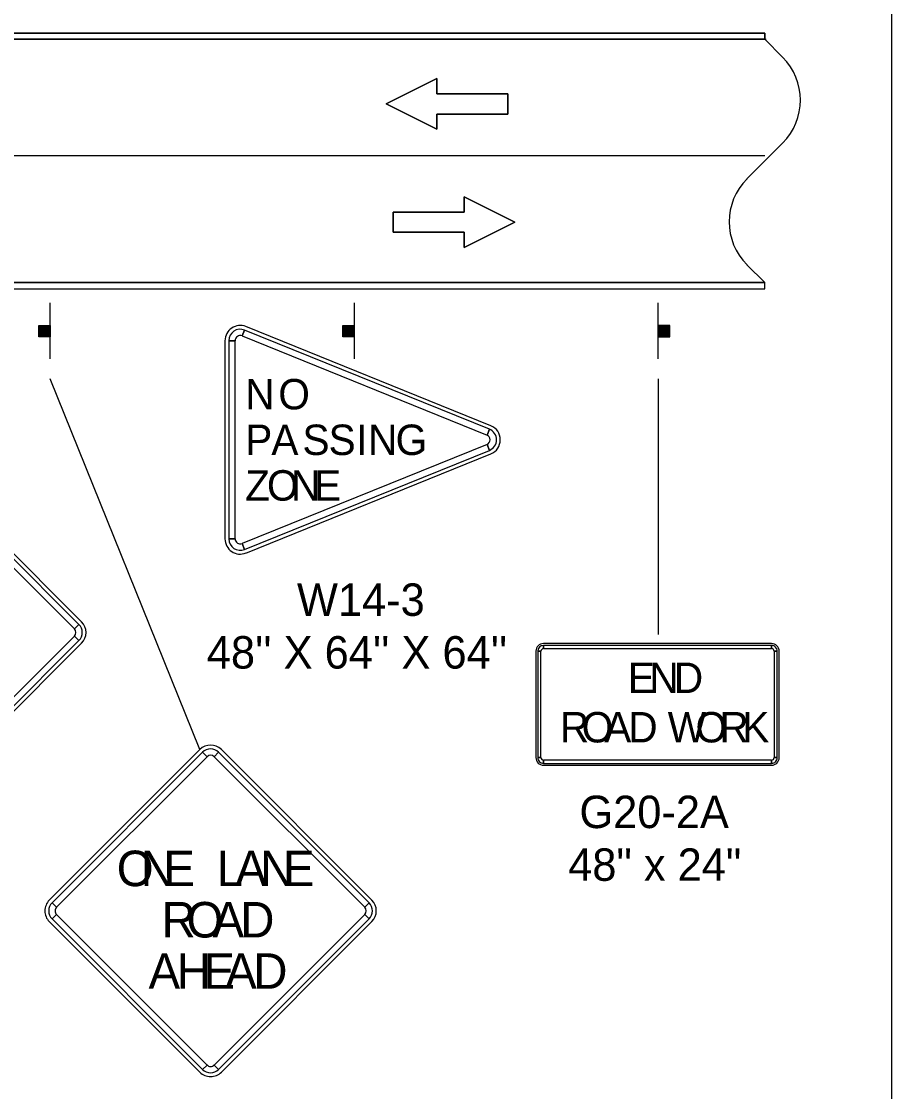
# Model space of a CAD drawing. Extents: x -2134934 to -2119606, y -2139046 to -2137036.
# Drawn here: x -2132229 to -2131799, y -2138064 to -2137536 of the extents above; entities that cross this region are included whole.
import ezdxf

# ---------------------------------------------------------------- set-up
doc = ezdxf.new("R2010")
doc.units = 0
for name, color, linetype in [('Default', 7, 'Continuous'), ('dsnStdLabel', 7, 'Continuous'), ('dsnStdLineWork', 7, 'Continuous'), ('Level 2', 7, 'Continuous')]:
    doc.layers.add(name, color=color, linetype=linetype)

msp = doc.modelspace()

# ---------------------------------------------------------------- linework, layer by layer
at = {"layer": 'Default'}
msp.add_lwpolyline([(-2134934.44, -2137035.95), (-2131799.45, -2137035.95), (-2131799.45, -2139045.94), (-2134934.44, -2139045.94)], close=True, dxfattribs=at)
at = {"layer": 'dsnStdLabel'}
for p, q in [((-2132119.84, -2137691.45), (-2132118.67, -2137688.56)), ((-2131997.15, -2137735.69), (-2132117.97, -2137686.82)), ((-2132128.28, -2137693.77), (-2132128.28, -2137791.52)), ((-2132126.41, -2137693.77), (-2132123.28, -2137693.77)), ((-2131997.85, -2137737.43), (-2131999.02, -2137740.33)), ((-2131999.02, -2137744.96), (-2131997.85, -2137747.86)), ((-2132117.97, -2137798.48), (-2131997.15, -2137749.6)), ((-2132198.99, -2137832.37), (-2132273.24, -2137758.12)), ((-2132123.28, -2137791.52), (-2132126.41, -2137791.52)), ((-2132118.67, -2137796.74), (-2132119.84, -2137793.84)), ((-2132200.32, -2137833.69), (-2132202.53, -2137835.9)), ((-2132202.53, -2137839.44), (-2132200.32, -2137841.65)), ((-2132273.24, -2137917.22), (-2132198.99, -2137842.98)), ((-2131974.91, -2137846.89), (-2131974.91, -2137899.39)), ((-2131973.97, -2137846.89), (-2131972.41, -2137846.89)), ((-2131858.66, -2137843.14), (-2131971.16, -2137843.14)), ((-2131971.16, -2137845.64), (-2131971.16, -2137844.08)), ((-2131858.66, -2137844.08), (-2131858.66, -2137845.64)), ((-2131857.41, -2137846.89), (-2131855.85, -2137846.89)), ((-2131854.91, -2137899.39), (-2131854.91, -2137846.89)), ((-2132140.68, -2137895.4), (-2132214.93, -2137969.64)), ((-2132139.36, -2137896.72), (-2132137.15, -2137898.93)), ((-2132133.61, -2137898.93), (-2132131.4, -2137896.72)), ((-2132055.83, -2137969.64), (-2132130.08, -2137895.4)), ((-2131972.41, -2137899.39), (-2131973.97, -2137899.39)), ((-2131855.85, -2137899.39), (-2131857.41, -2137899.39)), ((-2131971.16, -2137902.2), (-2131971.16, -2137900.64)), ((-2131971.16, -2137903.14), (-2131858.66, -2137903.14)), ((-2131858.66, -2137900.64), (-2131858.66, -2137902.2)), ((-2132211.4, -2137973.18), (-2132213.6, -2137970.97)), ((-2132057.16, -2137970.97), (-2132059.37, -2137973.18)), ((-2132213.6, -2137978.92), (-2132211.4, -2137976.71)), ((-2132059.37, -2137976.71), (-2132057.16, -2137978.92)), ((-2132214.93, -2137980.25), (-2132140.68, -2138054.5)), ((-2132130.08, -2138054.5), (-2132055.83, -2137980.25)), ((-2132137.15, -2138050.96), (-2132139.36, -2138053.17)), ((-2132131.4, -2138053.17), (-2132133.61, -2138050.96))]:
    msp.add_line(p, q, dxfattribs=at)
for points in [[(-2131997.85, -2137737.43), (-2132118.67, -2137688.56), (-2132119.84, -2137691.45), (-2131999.02, -2137740.33), (-2131997.85, -2137737.43)], [(-2132126.41, -2137693.77), (-2132126.41, -2137791.52), (-2132123.28, -2137791.52), (-2132123.28, -2137693.77), (-2132126.41, -2137693.77)], [(-2132118.67, -2137796.74), (-2131997.85, -2137747.86), (-2131999.02, -2137744.96), (-2132119.84, -2137793.84), (-2132118.67, -2137796.74)], [(-2132200.32, -2137833.69), (-2132274.57, -2137759.45), (-2132276.78, -2137761.66), (-2132202.53, -2137835.9), (-2132200.32, -2137833.69)], [(-2132274.57, -2137915.9), (-2132200.32, -2137841.65), (-2132202.53, -2137839.44), (-2132276.78, -2137913.69), (-2132274.57, -2137915.9)], [(-2131973.97, -2137846.89), (-2131973.97, -2137899.39), (-2131972.41, -2137899.39), (-2131972.41, -2137846.89), (-2131973.97, -2137846.89)], [(-2131858.66, -2137844.08), (-2131971.16, -2137844.08), (-2131971.16, -2137845.64), (-2131858.66, -2137845.64), (-2131858.66, -2137844.08)], [(-2131855.85, -2137899.39), (-2131855.85, -2137846.89), (-2131857.41, -2137846.89), (-2131857.41, -2137899.39), (-2131855.85, -2137899.39)], [(-2132139.36, -2137896.72), (-2132213.6, -2137970.97), (-2132211.4, -2137973.18), (-2132137.15, -2137898.93), (-2132139.36, -2137896.72)], [(-2132057.16, -2137970.97), (-2132131.4, -2137896.72), (-2132133.61, -2137898.93), (-2132059.37, -2137973.18), (-2132057.16, -2137970.97)], [(-2131971.16, -2137902.2), (-2131858.66, -2137902.2), (-2131858.66, -2137900.64), (-2131971.16, -2137900.64), (-2131971.16, -2137902.2)], [(-2132213.6, -2137978.92), (-2132139.36, -2138053.17), (-2132137.15, -2138050.96), (-2132211.4, -2137976.71), (-2132213.6, -2137978.92)], [(-2132131.4, -2138053.17), (-2132057.16, -2137978.92), (-2132059.37, -2137976.71), (-2132133.61, -2138050.96), (-2132131.4, -2138053.17)]]:
    msp.add_lwpolyline(points, close=True, dxfattribs=at)
for centre, radius, start, end in [((-2132120.78, -2137693.77), 7.5, 67.9757, 179.9998), ((-2132120.78, -2137693.77), 5.62, 67.9757, 179.9998), ((-2132120.78, -2137693.77), 2.5, 67.9757, 179.9998), ((-2131999.96, -2137742.65), 7.5, 292.0246, 67.976), ((-2131999.96, -2137742.65), 2.5, 292.0246, 67.9754), ((-2131999.96, -2137742.65), 5.62, 292.0246, 67.9754), ((-2132120.78, -2137791.52), 7.5, 179.9998, 292.0246), ((-2132120.78, -2137791.52), 5.62, 179.9998, 292.0246), ((-2132120.78, -2137791.52), 2.5, 179.9998, 292.0246), ((-2132204.3, -2137837.67), 2.5, 315.0002, 44.9998), ((-2132204.3, -2137837.67), 5.62, 315.0002, 44.9998), ((-2132204.3, -2137837.67), 7.5, 315.0002, 44.9998), ((-2131971.16, -2137846.89), 3.75, 90.0002, 179.9998), ((-2131971.16, -2137846.89), 2.81, 90.0002, 179.9998), ((-2131971.16, -2137846.89), 1.25, 90.0002, 179.9998), ((-2131858.66, -2137846.89), 3.75, 0, 90.0002), ((-2131858.66, -2137846.89), 2.81, 0, 90.0002), ((-2131858.66, -2137846.89), 1.25, 0, 90.0002), ((-2132135.38, -2137900.7), 7.5, 45, 134.9997), ((-2132135.38, -2137900.7), 5.62, 45, 134.9997), ((-2132135.38, -2137900.7), 2.5, 45, 134.9997), ((-2131971.16, -2137899.39), 3.75, 179.9998, 270.0001), ((-2131971.16, -2137899.39), 2.81, 179.9998, 270.0001), ((-2131971.16, -2137899.39), 1.25, 179.9998, 270.0001), ((-2131858.66, -2137899.39), 3.75, 270.0001, 0.0003), ((-2131858.66, -2137899.39), 2.81, 270.0001, 0.0003), ((-2131858.66, -2137899.39), 1.25, 270.0001, 0.0003), ((-2132209.63, -2137974.95), 7.5, 134.9997, 225), ((-2132209.63, -2137974.95), 5.62, 134.9997, 225), ((-2132209.63, -2137974.95), 2.5, 134.9997, 225), ((-2132061.14, -2137974.95), 2.5, 315.0002, 44.9998), ((-2132061.14, -2137974.95), 5.62, 315.0002, 44.9998), ((-2132061.14, -2137974.95), 7.5, 315.0002, 44.9998), ((-2132135.38, -2138049.19), 2.5, 225, 315.0002), ((-2132135.38, -2138049.19), 7.5, 225, 315.0002), ((-2132135.38, -2138049.19), 5.62, 225, 315.0002)]:
    msp.add_arc(centre, radius, start, end, dxfattribs=at)
at = {"layer": 'dsnStdLineWork'}
for p, q in [((-2131861.99, -2137542.16), (-2132547.01, -2137542.16)), ((-2132509.45, -2137545.16), (-2131861.99, -2137545.16)), ((-2131861.99, -2137542.16), (-2131861.99, -2137545.16)), ((-2131861.99, -2137545.16), (-2131861.99, -2137542.16)), ((-2131861.95, -2137602.66), (-2132514.45, -2137602.66)), ((-2133364.44, -2137665.16), (-2131861.99, -2137665.16)), ((-2133364.44, -2137665.16), (-2131861.99, -2137665.16)), ((-2131861.99, -2137665.16), (-2132441.05, -2137665.16)), ((-2131861.99, -2137668.16), (-2131861.99, -2137665.16)), ((-2131861.99, -2137668.16), (-2131861.99, -2137665.16)), ((-2133364.44, -2137668.16), (-2131861.99, -2137668.16)), ((-2132442.06, -2137668.16), (-2131861.99, -2137668.16))]:
    msp.add_line(p, q, dxfattribs=at)
for points in [[(-2133174.44, -2137542.16), (-2131861.99, -2137542.16)], [(-2133174.44, -2137545.16), (-2131861.99, -2137545.16)], [(-2133173.75, -2137545.16), (-2131861.29, -2137545.16)]]:
    msp.add_lwpolyline(points, dxfattribs=at)
at = {"layer": 'Level 2'}
for p, q in [((-2131861.99, -2137545.16), (-2133174.44, -2137545.16)), ((-2131853.21, -2137553.94), (-2131861.99, -2137545.16)), ((-2131853.2, -2137553.95), (-2131861.99, -2137545.16)), ((-2131870.78, -2137613.94), (-2131853.21, -2137596.37)), ((-2131870.78, -2137613.95), (-2131853.2, -2137596.37)), ((-2131861.99, -2137665.16), (-2131870.78, -2137656.37)), ((-2131861.99, -2137665.16), (-2131870.78, -2137656.37)), ((-2133364.44, -2137665.16), (-2131861.99, -2137665.16)), ((-2132214.45, -2137702.66), (-2132214.45, -2137675.16)), ((-2132064.45, -2137702.66), (-2132064.45, -2137675.16)), ((-2131914.64, -2137702.66), (-2131914.64, -2137675.16)), ((-2132219.77, -2137691.8), (-2132219.77, -2137686.21)), ((-2132219.45, -2137686.21), (-2132219.45, -2137691.8)), ((-2132219.23, -2137691.8), (-2132219.23, -2137686.21)), ((-2132218.91, -2137686.21), (-2132218.91, -2137691.8)), ((-2132218.69, -2137691.8), (-2132218.7, -2137686.21)), ((-2132218.27, -2137686.21), (-2132218.25, -2137691.8)), ((-2132218.05, -2137691.8), (-2132218.05, -2137686.21)), ((-2132217.62, -2137686.21), (-2132217.62, -2137691.8)), ((-2132217.24, -2137691.8), (-2132217.24, -2137686.21)), ((-2132216.92, -2137686.21), (-2132216.9, -2137691.8)), ((-2132216.7, -2137691.8), (-2132216.7, -2137686.21)), ((-2132216.43, -2137686.21), (-2132216.43, -2137691.8)), ((-2132216.1, -2137691.8), (-2132216.1, -2137686.21)), ((-2132215.89, -2137686.21), (-2132215.89, -2137691.8)), ((-2132215.67, -2137691.8), (-2132215.67, -2137686.21)), ((-2132215.4, -2137686.21), (-2132215.4, -2137691.8)), ((-2132215.14, -2137691.8), (-2132215.14, -2137686.21)), ((-2132214.86, -2137686.21), (-2132214.86, -2137691.8)), ((-2132069.77, -2137691.8), (-2132069.77, -2137686.21)), ((-2132069.45, -2137686.21), (-2132069.45, -2137691.8)), ((-2132069.23, -2137691.8), (-2132069.23, -2137686.21)), ((-2132068.91, -2137686.21), (-2132068.91, -2137691.8)), ((-2132068.69, -2137691.8), (-2132068.7, -2137686.21)), ((-2132068.27, -2137686.21), (-2132068.25, -2137691.8)), ((-2132068.05, -2137691.8), (-2132068.05, -2137686.21)), ((-2132067.62, -2137686.21), (-2132067.62, -2137691.8)), ((-2132067.24, -2137691.8), (-2132067.24, -2137686.21)), ((-2132066.92, -2137686.21), (-2132066.9, -2137691.8)), ((-2132066.7, -2137691.8), (-2132066.7, -2137686.21)), ((-2132066.43, -2137686.21), (-2132066.43, -2137691.8)), ((-2132066.1, -2137691.8), (-2132066.1, -2137686.21)), ((-2132065.89, -2137686.21), (-2132065.89, -2137691.8)), ((-2132065.67, -2137691.8), (-2132065.67, -2137686.21)), ((-2132065.4, -2137686.21), (-2132065.4, -2137691.8)), ((-2132065.14, -2137691.8), (-2132065.14, -2137686.21)), ((-2132064.86, -2137686.21), (-2132064.86, -2137691.8)), ((-2131914.22, -2137686.21), (-2131914.22, -2137691.8)), ((-2131913.94, -2137691.8), (-2131913.94, -2137686.21)), ((-2131913.68, -2137686.21), (-2131913.68, -2137691.8)), ((-2131913.42, -2137691.8), (-2131913.42, -2137686.21)), ((-2131913.19, -2137686.21), (-2131913.19, -2137691.8)), ((-2131912.99, -2137691.8), (-2131912.99, -2137686.21)), ((-2131912.65, -2137686.21), (-2131912.65, -2137691.8)), ((-2131912.39, -2137691.8), (-2131912.39, -2137686.21)), ((-2131912.16, -2137686.21), (-2131912.18, -2137691.8)), ((-2131911.84, -2137691.8), (-2131911.84, -2137686.21)), ((-2131911.47, -2137686.21), (-2131911.47, -2137691.8)), ((-2131911.04, -2137691.8), (-2131911.04, -2137686.21)), ((-2131910.81, -2137686.21), (-2131910.83, -2137691.8)), ((-2131910.4, -2137691.8), (-2131910.38, -2137686.21)), ((-2131910.17, -2137686.21), (-2131910.17, -2137691.8)), ((-2131909.85, -2137691.8), (-2131909.85, -2137686.21)), ((-2131909.63, -2137686.21), (-2131909.63, -2137691.8)), ((-2131909.31, -2137691.8), (-2131909.31, -2137686.21)), ((-2132140.68, -2137895.4), (-2132214.45, -2137712.66)), ((-2131914.45, -2137838.71), (-2131914.45, -2137712.66))]:
    msp.add_line(p, q, dxfattribs=at)
for points in [[(-2131988.74, -2137582), (-2131988.74, -2137572), (-2132023.74, -2137572), (-2132023.74, -2137564.5), (-2132048.74, -2137577), (-2132023.74, -2137589.5), (-2132023.74, -2137582)], [(-2132045.26, -2137630.33), (-2132045.26, -2137640.33), (-2132010.26, -2137640.33), (-2132010.26, -2137647.83), (-2131985.26, -2137635.33), (-2132010.26, -2137622.83), (-2132010.26, -2137630.33)], [(-2132214.54, -2137686.21), (-2132214.54, -2137691.84), (-2132220.17, -2137691.84), (-2132220.17, -2137686.21)], [(-2132064.54, -2137686.21), (-2132064.54, -2137691.84), (-2132070.17, -2137691.84), (-2132070.17, -2137686.21)], [(-2131914.54, -2137686.21), (-2131914.54, -2137691.84), (-2131908.92, -2137691.84), (-2131908.92, -2137686.21)]]:
    msp.add_lwpolyline(points, close=True, dxfattribs=at)
for points in [[(-2132023.74, -2137582), (-2132023.74, -2137589.5), (-2132048.74, -2137577), (-2132023.74, -2137564.5), (-2132023.74, -2137572), (-2131988.74, -2137572), (-2131988.74, -2137582), (-2132023.74, -2137582)], [(-2132010.26, -2137630.33), (-2132010.26, -2137622.83), (-2131985.26, -2137635.33), (-2132010.26, -2137647.83), (-2132010.26, -2137640.33), (-2132045.26, -2137640.33), (-2132045.26, -2137630.33), (-2132010.26, -2137630.33)]]:
    msp.add_lwpolyline(points, dxfattribs=at)
for centre, start, end in [((-2131874.42, -2137575.16), 315, 45), ((-2131874.42, -2137575.16), 315, 45), ((-2131849.56, -2137635.16), 135, 225), ((-2131849.56, -2137635.16), 135, 225)]:
    msp.add_arc(centre, 30, start, end, dxfattribs=at)

# ---------------------------------------------------------------- texts
at = {"layer": 'dsnStdLabel'}
for s, height, p in [('N', 15, (-2132118.31, -2137727.65)), ('O', 15, (-2132101.97, -2137727.65)), ('P', 15, (-2132118.31, -2137750.15)), ('A', 15, (-2132105.42, -2137750.15)), ('S', 15, (-2132090.07, -2137750.15)), ('S', 15, (-2132077.18, -2137750.15)), ('I', 15, (-2132063.59, -2137750.15)), ('N', 15, (-2132057.73, -2137750.15)), ('G', 15, (-2132044.13, -2137750.15)), ('O', 15, (-2132107.58, -2137772.65)), ('Z', 15, (-2132118.31, -2137772.65)), ('N', 15, (-2132095.75, -2137772.65)), ('E', 15, (-2132084.38, -2137772.65)), ('W14-3', 16, (-2132092.77, -2137829.48)), ("48'' X 64'' X 64''", 16, (-2132137.26, -2137855.47)), ('E', 15, (-2131929.58, -2137867.51)), ('N', 15, (-2131918.96, -2137867.51)), ('D', 15, (-2131906.88, -2137867.51)), ('R', 15, (-2131963.05, -2137891.89)), ('O', 15, (-2131952.36, -2137891.89)), ('A', 15, (-2131941.21, -2137891.89)), ('D', 15, (-2131929.35, -2137891.89)), ('W', 15, (-2131909.9, -2137891.89)), ('O', 15, (-2131896.16, -2137891.89)), ('R', 15, (-2131884.4, -2137891.89)), ('K', 15, (-2131873.1, -2137891.89)), ('G20-2A', 16, (-2131953.44, -2137934.14)), ('O', 17.5, (-2132181.67, -2137962.76)), ('N', 17.5, (-2132169.89, -2137962.76)), ('E', 17.5, (-2132158.66, -2137962.76)), ('L', 17.5, (-2132132.41, -2137962.76)), ('A', 17.5, (-2132123.22, -2137962.76)), ('N', 17.5, (-2132110.95, -2137962.76)), ('E', 17.5, (-2132099.72, -2137962.76)), ('48" x 24"', 16, (-2131958.97, -2137960.14)), ('R', 17.5, (-2132159.56, -2137988.07)), ('O', 17.5, (-2132147.27, -2137988.07)), ('A', 17.5, (-2132134.43, -2137988.07)), ('D', 17.5, (-2132120.78, -2137988.07)), ('A', 17.5, (-2132166, -2138013.38)), ('H', 17.5, (-2132152.13, -2138013.38)), ('E', 17.5, (-2132138.91, -2138013.38)), ('A', 17.5, (-2132128.2, -2138013.38)), ('D', 17.5, (-2132114.34, -2138013.38))]:
    msp.add_text(s, height=height, dxfattribs=at).set_placement(p)

doc.saveas('drawing.dxf')
